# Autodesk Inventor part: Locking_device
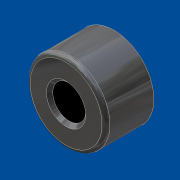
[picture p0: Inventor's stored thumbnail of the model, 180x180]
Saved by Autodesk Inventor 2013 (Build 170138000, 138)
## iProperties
Shininess: 69.0
Length Units: 11269
Angle Units: 11279
Time Units: 11290
Mass Units: 11283
Length Display Precision: 3
Angle Display Precision: 2
Created: 2001-04
Part Number: Locking_device
Material: Standard
Document SubType Name: Modellieren
Designer: dl
Density: 1 g/cm^3
Density: 0.0
Volumn: 0.0
Area: 0.0
PropertySet Name: Model Information
Control State: 0
Master: False
Checked Out: False
Author: dl
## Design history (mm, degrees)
body "Solid1"
sketch "Sketch1"
  geometry: C1 r 5 at (0, 0)
  constraints: 1 centre point
extrude "Extrusion1" new body sketch "Sketch1" distance "d0" = 6; taper "d1" = 0 deg
sketch "Sketch2"
  geometry: C1 r 4.5 at (0, 0) reference; 1 further point
  constraints: 1 coincident
fillet "Fillet1" dims "d2" = 0.5
hole "Hole1" sketch "Sketch2" diameter "d3" = 4.134; stored, may be unused: countersink angle "d7" = 60 deg, drill point angle "d9" = 118 deg; dims "d4" = 6, "d5" = 4, "d6" = 2, "d8" = 8
chamfer "Chamfer1" distance "d10" = 0.4; stored, may be unused: second distance "d11" = 0.4, angle "d12" = 45 deg
